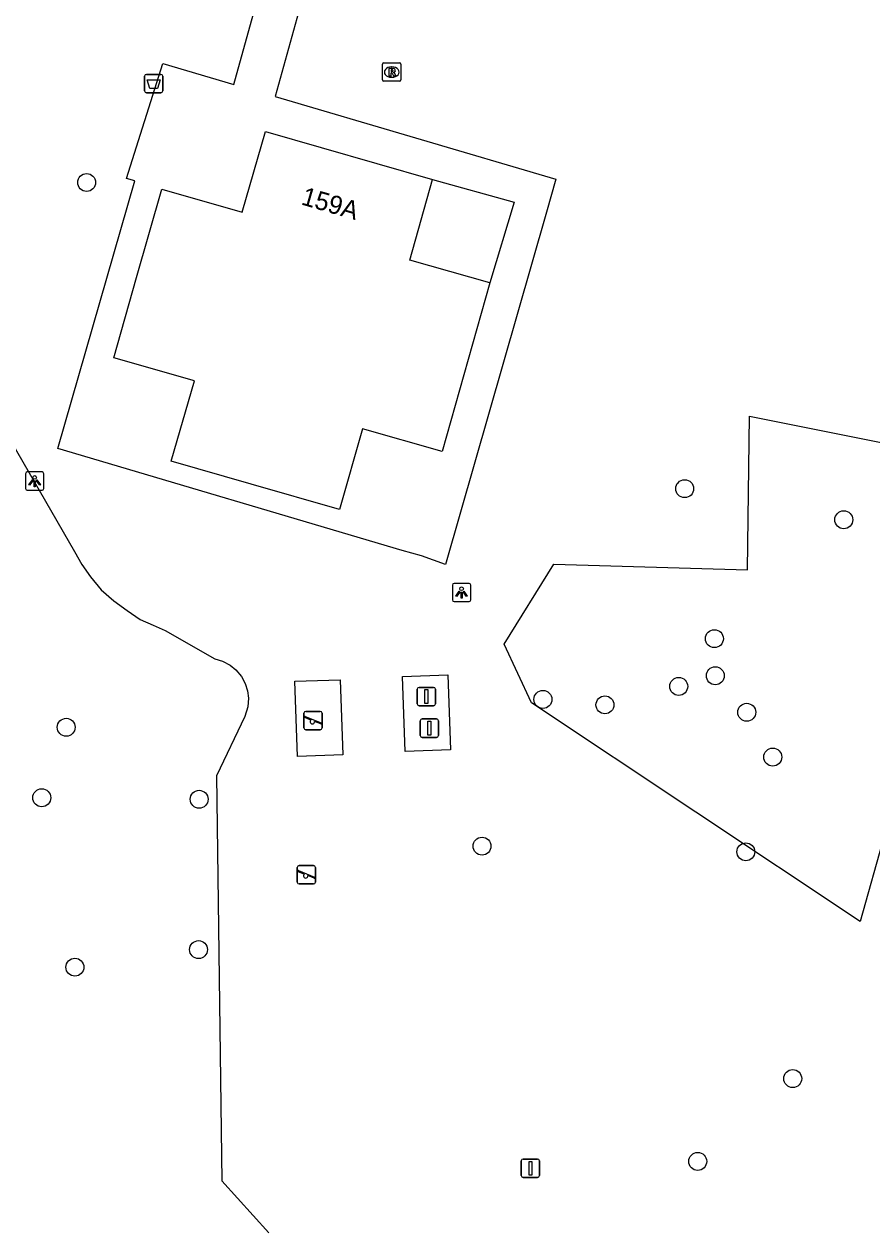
# Model space of a CAD drawing. Extents: x 161258 to 161838, y 380836 to 381727.
# Drawn here: x 161379.4 to 161425.6, y 381591.6 to 381657.1 of the extents above; entities that cross this region are included whole.
import ezdxf

# ---------------------------------------------------------------- set-up
doc = ezdxf.new("R2010")
doc.units = 0
for name, color, linetype in [('IMGEO_Afsluitpaal', 7, 'Continuous'), ('IMGEO_Afvalbak', 7, 'Continuous'), ('IMGEO_Boom', 7, 'Continuous'), ('IMGEO_Gemengd_bos', 7, 'Continuous'), ('IMGEO_Groenvoorziening', 7, 'Continuous'), ('IMGEO_Lichtpunt', 7, 'Continuous'), ('IMGEO_Pand', 7, 'Continuous'), ('IMGEO_Pand_nummerreeks', 7, 'Continuous'), ('IMGEO_Rioolput', 7, 'Continuous'), ('IMGEO_Speelvoorziening', 7, 'Continuous'), ('IMGEO_Vlaggenmast', 7, 'Continuous'), ('IMGEO_Voetpad_open', 7, 'Continuous')]:
    doc.layers.add(name, color=color, linetype=linetype)

msp = doc.modelspace()

# ---------------------------------------------------------------- linework, layer by layer
at = {"layer": 'IMGEO_Afsluitpaal'}
for p, q in [((161400.856, 381620.042), (161400.856, 381620.842)), ((161400.856, 381620.842), (161400.856, 381620.042)), ((161400.956, 381620.942), (161401.746, 381620.942)), ((161401.746, 381620.942), (161400.956, 381620.942)), ((161401.846, 381620.842), (161401.846, 381620.042)), ((161401.846, 381620.042), (161401.846, 381620.842)), ((161401.746, 381619.942), (161400.956, 381619.942)), ((161400.956, 381619.942), (161401.746, 381619.942)), ((161401.023, 381618.318), (161401.023, 381619.118)), ((161401.023, 381619.118), (161401.023, 381618.318)), ((161401.123, 381619.218), (161401.913, 381619.218)), ((161401.913, 381619.218), (161401.123, 381619.218)), ((161402.013, 381619.118), (161402.013, 381618.318)), ((161402.013, 381618.318), (161402.013, 381619.118)), ((161401.913, 381618.218), (161401.123, 381618.218)), ((161401.123, 381618.218), (161401.913, 381618.218))]:
    msp.add_line(p, q, dxfattribs=at)
for points in [[(161401.276, 381620.817), (161401.426, 381620.817), (161401.426, 381620.067), (161401.276, 381620.067), (161401.276, 381620.817)], [(161401.443, 381619.093), (161401.593, 381619.093), (161401.593, 381618.343), (161401.443, 381618.343), (161401.443, 381619.093)]]:
    msp.add_lwpolyline(points, dxfattribs=at)
for centre, start, end in [((161400.956, 381620.842), 90, 180), ((161400.956, 381620.842), 90, 180), ((161401.746, 381620.842), 0, 90), ((161401.746, 381620.842), 360, 90), ((161400.956, 381620.042), 180, 270), ((161400.956, 381620.042), 180, 270), ((161401.746, 381620.042), 270, 0), ((161401.746, 381620.042), 270, 0), ((161401.123, 381619.118), 90, 180), ((161401.123, 381619.118), 90, 180), ((161401.913, 381619.118), 0, 90), ((161401.913, 381619.118), 360, 90), ((161401.123, 381618.318), 180, 270), ((161401.123, 381618.318), 180, 270), ((161401.913, 381618.318), 270, 0), ((161401.913, 381618.318), 270, 0)]:
    msp.add_arc(centre, 0.1, start, end, dxfattribs=at)
at = {"layer": 'IMGEO_Afvalbak'}
for p, q in [((161386, 381653.421), (161386, 381654.221)), ((161386, 381654.221), (161386, 381653.421)), ((161386.1, 381654.321), (161386.89, 381654.321)), ((161386.89, 381654.321), (161386.1, 381654.321)), ((161386.99, 381654.221), (161386.99, 381653.421)), ((161386.99, 381653.421), (161386.99, 381654.221)), ((161386.89, 381653.321), (161386.1, 381653.321)), ((161386.1, 381653.321), (161386.89, 381653.321))]:
    msp.add_line(p, q, dxfattribs=at)
msp.add_lwpolyline([(161386.143, 381654.035), (161386.847, 381654.035), (161386.698, 381653.565), (161386.292, 381653.565), (161386.143, 381654.035)], dxfattribs=at)
for centre, start, end in [((161386.1, 381654.221), 90, 180), ((161386.1, 381654.221), 90, 180), ((161386.89, 381654.221), 0, 90), ((161386.89, 381654.221), 360, 90), ((161386.1, 381653.421), 180, 270), ((161386.1, 381653.421), 180, 270), ((161386.89, 381653.421), 270, 0), ((161386.89, 381653.421), 270, 0)]:
    msp.add_arc(centre, 0.1, start, end, dxfattribs=at)
at = {"layer": 'IMGEO_Boom'}
for centre in [(161382.846, 381648.438), (161415.429, 381631.761), (161424.097, 381630.07), (161417.047, 381623.592), (161417.098, 381621.573), (161415.103, 381620.993), (161407.705, 381620.285), (161411.085, 381619.988), (161418.812, 381619.583), (161381.732, 381618.765), (161420.227, 381617.142), (161380.399, 381614.928), (161388.976, 381614.844), (161404.387, 381612.292), (161418.761, 381611.984), (161388.942, 381606.656), (161382.205, 381605.701), (161421.315, 381599.635), (161416.138, 381595.122)]:
    msp.add_circle(centre, 0.489, dxfattribs=at)
at = {"layer": 'IMGEO_Gemengd_bos'}
for points in [[(161376.186, 381638.709), (161382.181, 381628.334), (161382.583, 381627.63), (161383.057, 381626.955), (161383.645, 381626.251), (161384.32, 381625.648), (161385.052, 381625.131), (161385.77, 381624.643), (161386.473, 381624.327), (161387.123, 381624.033), (161389.838, 381622.503), (161390.242, 381622.367), (161390.658, 381622.158), (161390.981, 381621.893), (161391.275, 381621.526), (161391.491, 381621.146), (161391.605, 381620.751), (161391.656, 381620.356), (161391.634, 381619.875), (161391.46, 381619.355), (161389.922, 381616.123), (161390.219, 381594.066), (161392.773, 381591.226)], [(161428.272, 381612.541), (161426.307, 381612.909), (161424.991, 381608.183), (161407.091, 381620.098), (161405.585, 381623.296), (161408.294, 381627.656), (161418.846, 381627.333), (161418.967, 381635.706), (161426.68, 381634.173)]]:
    msp.add_lwpolyline(points, dxfattribs=at)
at = {"layer": 'IMGEO_Groenvoorziening'}
for points in [[(161396.654, 381621.359), (161396.798, 381617.269), (161394.33, 381617.182), (161394.185, 381621.271), (161396.654, 381621.359)], [(161402.53, 381621.627), (161402.675, 381617.537), (161400.206, 381617.45), (161400.062, 381621.539), (161402.53, 381621.627)]]:
    msp.add_lwpolyline(points, dxfattribs=at)
at = {"layer": 'IMGEO_Lichtpunt'}
for p, q in [((161379.516, 381632.577), (161379.516, 381631.77)), ((161379.516, 381632.577), (161379.516, 381631.77)), ((161380.418, 381632.672), (161379.61, 381632.672)), ((161380.418, 381632.672), (161379.61, 381632.672)), ((161380.512, 381631.77), (161380.512, 381632.577)), ((161380.512, 381631.77), (161380.512, 381632.577)), ((161379.61, 381631.676), (161380.418, 381631.676)), ((161379.61, 381631.676), (161380.418, 381631.676)), ((161403.678, 381626.606), (161402.87, 381626.606)), ((161403.678, 381626.606), (161402.87, 381626.606)), ((161402.776, 381626.511), (161402.776, 381625.704)), ((161402.776, 381626.511), (161402.776, 381625.704)), ((161403.772, 381625.704), (161403.772, 381626.511)), ((161403.772, 381625.704), (161403.772, 381626.511)), ((161402.87, 381625.61), (161403.678, 381625.61)), ((161402.87, 381625.61), (161403.678, 381625.61))]:
    msp.add_line(p, q, dxfattribs=at)
for points in [[(161379.89, 381632.241), (161379.929, 381632.213), (161379.741, 381631.951), (161379.703, 381631.978), (161379.89, 381632.241)], [(161379.992, 381632.193), (161380.039, 381632.193), (161380.039, 381631.871), (161379.992, 381631.871), (161379.992, 381632.193)], [(161380.102, 381632.213), (161380.14, 381632.24), (161380.327, 381631.978), (161380.288, 381631.95), (161380.102, 381632.213)], [(161403.15, 381626.175), (161403.189, 381626.147), (161403.001, 381625.885), (161402.963, 381625.912), (161403.15, 381626.175)], [(161403.252, 381626.127), (161403.299, 381626.127), (161403.299, 381625.805), (161403.252, 381625.805), (161403.252, 381626.127)], [(161403.362, 381626.147), (161403.4, 381626.174), (161403.587, 381625.912), (161403.548, 381625.884), (161403.362, 381626.147)]]:
    msp.add_lwpolyline(points, dxfattribs=at)
for centre in [(161380.015, 381632.375), (161403.275, 381626.309)]:
    msp.add_circle(centre, 0.0994, dxfattribs=at)
for centre, start, end in [((161379.61, 381632.577), 90, 180), ((161379.61, 381632.577), 90, 180), ((161380.418, 381632.577), 0, 90), ((161380.418, 381632.577), 0, 90), ((161379.61, 381631.77), 180, 270), ((161379.61, 381631.77), 180, 270), ((161380.418, 381631.77), 270, 0), ((161380.418, 381631.77), 270, 360), ((161402.87, 381626.511), 90, 180), ((161402.87, 381626.511), 90, 180), ((161403.678, 381626.511), 0, 90), ((161403.678, 381626.511), 0, 90), ((161402.87, 381625.704), 180, 270), ((161402.87, 381625.704), 180, 270), ((161403.678, 381625.704), 270, 0), ((161403.678, 381625.704), 270, 360)]:
    msp.add_arc(centre, 0.0946, start, end, dxfattribs=at)
at = {"layer": 'IMGEO_Pand'}
for points in [[(161404.821, 381642.967), (161402.225, 381633.783), (161397.868, 381635.027), (161396.616, 381630.626), (161391.811, 381632.008), (161387.454, 381633.261), (161388.72, 381637.631), (161384.329, 381638.884), (161385.571, 381643.267), (161386.934, 381648.077), (161391.312, 381646.822), (161392.583, 381651.21), (161401.691, 381648.594)], [(161404.821, 381642.967), (161400.446, 381644.203), (161401.691, 381648.594)]]:
    msp.add_lwpolyline(points, dxfattribs=at)
at = {"layer": 'IMGEO_Rioolput'}
for p, q in [((161398.968, 381654.025), (161398.968, 381654.877)), ((161399.043, 381654.951), (161399.895, 381654.951)), ((161399.456, 381654.731), (161399.481, 381654.731)), ((161399.969, 381654.877), (161399.969, 381654.025)), ((161399.479, 381654.171), (161399.454, 381654.171)), ((161399.895, 381653.951), (161399.043, 381653.951))]:
    msp.add_line(p, q, dxfattribs=at)
for points in [[(161398.968, 381654.025), (161398.968, 381654.877)], [(161399.043, 381654.951), (161399.895, 381654.951)], [(161399.969, 381654.877), (161399.969, 381654.025)], [(161399.557, 381654.649), (161399.305, 381654.651), (161399.305, 381654.251)], [(161399.305, 381654.251), (161399.429, 381654.251), (161399.429, 381654.413), (161399.44, 381654.413)], [(161399.483, 381654.57), (161399.429, 381654.57), (161399.429, 381654.489)], [(161399.429, 381654.489), (161399.481, 381654.489)], [(161399.487, 381654.384), (161399.558, 381654.251), (161399.698, 381654.251), (161399.633, 381654.377)], [(161399.895, 381653.951), (161399.043, 381653.951)]]:
    msp.add_lwpolyline(points, dxfattribs=at)
for centre, radius, start, end in [((161399.045, 381654.875), 0.0765, 91.55205, 178.44795), ((161399.045, 381654.875), 0.0765, 91.55205, 178.44795), ((161399.893, 381654.875), 0.0765, 1.55205, 88.44795), ((161399.893, 381654.875), 0.0765, 1.55205, 88.44795), ((161399.439, 381654.36), 0.0533, 26.02933, 88.69889), ((161399.465, 381654.678), 0.19, 274.7715, 282.96867), ((161399.489, 381654.474), 0.0964, 77.00612, 93.18647), ((161399.503, 381654.531), 0.0378, 276.66336, 79.67722), ((161399.556, 381654.539), 0.109, 350.36119, 89.41601), ((161399.554, 381654.539), 0.112, 277.58423, 350.98172), ((161399.538, 381654.324), 0.108, 29.51342, 73.79051), ((161399.045, 381654.027), 0.0765, 181.55205, 268.44795), ((161399.045, 381654.027), 0.0765, 181.55205, 268.44795), ((161399.893, 381654.027), 0.0765, 271.55205, 358.44795), ((161399.893, 381654.027), 0.0765, 271.55205, 358.44795)]:
    msp.add_arc(centre, radius, start, end, dxfattribs=at)
for centre, major_axis, ratio, start_param, end_param in [((161399.455, 381654.451), (-0.387, 0.002), 0.722429, 4.712389, 7.853982), ((161399.48, 381654.451), (-0.39, 0.002), 0.717154, 1.570796, 4.712389)]:
    msp.add_ellipse(centre, major_axis=major_axis, ratio=ratio, start_param=start_param, end_param=end_param, dxfattribs=at)
at = {"layer": 'IMGEO_Speelvoorziening'}
for p, q in [((161394.682, 381618.735), (161394.682, 381619.535)), ((161394.682, 381619.535), (161394.682, 381618.735)), ((161394.782, 381619.635), (161395.572, 381619.635)), ((161395.572, 381619.635), (161394.782, 381619.635)), ((161395.672, 381619.535), (161395.672, 381618.735)), ((161395.672, 381618.735), (161395.672, 381619.535)), ((161395.065, 381619.163), (161394.726, 381619.3)), ((161394.751, 381619.36), (161395.627, 381619.007)), ((161395.603, 381618.947), (161395.263, 381619.084)), ((161395.572, 381618.635), (161394.782, 381618.635)), ((161394.782, 381618.635), (161395.572, 381618.635)), ((161394.321, 381610.337), (161394.321, 381611.137)), ((161394.321, 381611.137), (161394.321, 381610.337)), ((161394.704, 381610.765), (161394.365, 381610.902)), ((161394.39, 381610.962), (161395.266, 381610.609)), ((161394.421, 381611.237), (161395.211, 381611.237)), ((161395.211, 381611.237), (161394.421, 381611.237)), ((161395.311, 381611.137), (161395.311, 381610.337)), ((161395.311, 381610.337), (161395.311, 381611.137)), ((161395.211, 381610.237), (161394.421, 381610.237)), ((161394.421, 381610.237), (161395.211, 381610.237)), ((161395.242, 381610.549), (161394.902, 381610.686))]:
    msp.add_line(p, q, dxfattribs=at)
for centre, radius, start, end in [((161394.782, 381619.535), 0.1, 90, 180), ((161394.782, 381619.535), 0.1, 90, 180), ((161395.572, 381619.535), 0.1, 0, 90), ((161395.572, 381619.535), 0.1, 360, 90), ((161394.782, 381618.735), 0.1, 180, 270), ((161394.782, 381618.735), 0.1, 180, 270), ((161394.739, 381619.33), 0.0327, 68.07798, 248.07798), ((161395.144, 381619.073), 0.12, 130.99278, 5.16318), ((161395.572, 381618.735), 0.1, 270, 0), ((161395.572, 381618.735), 0.1, 270, 0), ((161395.615, 381618.977), 0.0327, 248.07798, 68.07798), ((161394.421, 381611.137), 0.1, 90, 180), ((161394.421, 381611.137), 0.1, 90, 180), ((161394.378, 381610.932), 0.0327, 68.07798, 248.07798), ((161395.211, 381611.137), 0.1, 0, 90), ((161395.211, 381611.137), 0.1, 360, 90), ((161394.421, 381610.337), 0.1, 180, 270), ((161394.421, 381610.337), 0.1, 180, 270), ((161394.783, 381610.675), 0.12, 130.99278, 5.16318), ((161395.211, 381610.337), 0.1, 270, 0), ((161395.211, 381610.337), 0.1, 270, 0), ((161395.254, 381610.579), 0.0327, 248.07798, 68.07798)]:
    msp.add_arc(centre, radius, start, end, dxfattribs=at)
at = {"layer": 'IMGEO_Vlaggenmast'}
for p, q in [((161406.529, 381594.347), (161406.529, 381595.147)), ((161406.529, 381595.147), (161406.529, 381594.347)), ((161406.629, 381595.247), (161407.419, 381595.247)), ((161407.419, 381595.247), (161406.629, 381595.247)), ((161407.519, 381595.147), (161407.519, 381594.347)), ((161407.519, 381594.347), (161407.519, 381595.147)), ((161407.419, 381594.247), (161406.629, 381594.247)), ((161406.629, 381594.247), (161407.419, 381594.247))]:
    msp.add_line(p, q, dxfattribs=at)
msp.add_lwpolyline([(161406.949, 381595.122), (161407.099, 381595.122), (161407.099, 381594.372), (161406.949, 381594.372), (161406.949, 381595.122)], dxfattribs=at)
for centre, start, end in [((161406.629, 381595.147), 90, 180), ((161406.629, 381595.147), 90, 180), ((161407.419, 381595.147), 0, 90), ((161407.419, 381595.147), 360, 90), ((161406.629, 381594.347), 180, 270), ((161406.629, 381594.347), 180, 270), ((161407.419, 381594.347), 270, 0), ((161407.419, 381594.347), 270, 0)]:
    msp.add_arc(centre, 0.1, start, end, dxfattribs=at)
at = {"layer": 'IMGEO_Voetpad_open'}
for points in [[(161396.659, 381665.882), (161393.126, 381653.115), (161408.406, 381648.613), (161407.893, 381646.823), (161402.4, 381627.633), (161401.084, 381628.097), (161400.041, 381628.391), (161381.277, 381633.951), (161385.48, 381648.52), (161385.02, 381648.657), (161387, 381654.92), (161390.867, 381653.781), (161394.382, 381666.485)], [(161401.691, 381648.594), (161406.142, 381647.362), (161404.821, 381642.967)]]:
    msp.add_lwpolyline(points, dxfattribs=at)

# ---------------------------------------------------------------- texts
at = {"layer": 'IMGEO_Pand_nummerreeks'}
msp.add_text('159A', height=1, rotation=343.97487, dxfattribs=at).set_placement((161394.484, 381647.251))

doc.saveas('drawing.dxf')
